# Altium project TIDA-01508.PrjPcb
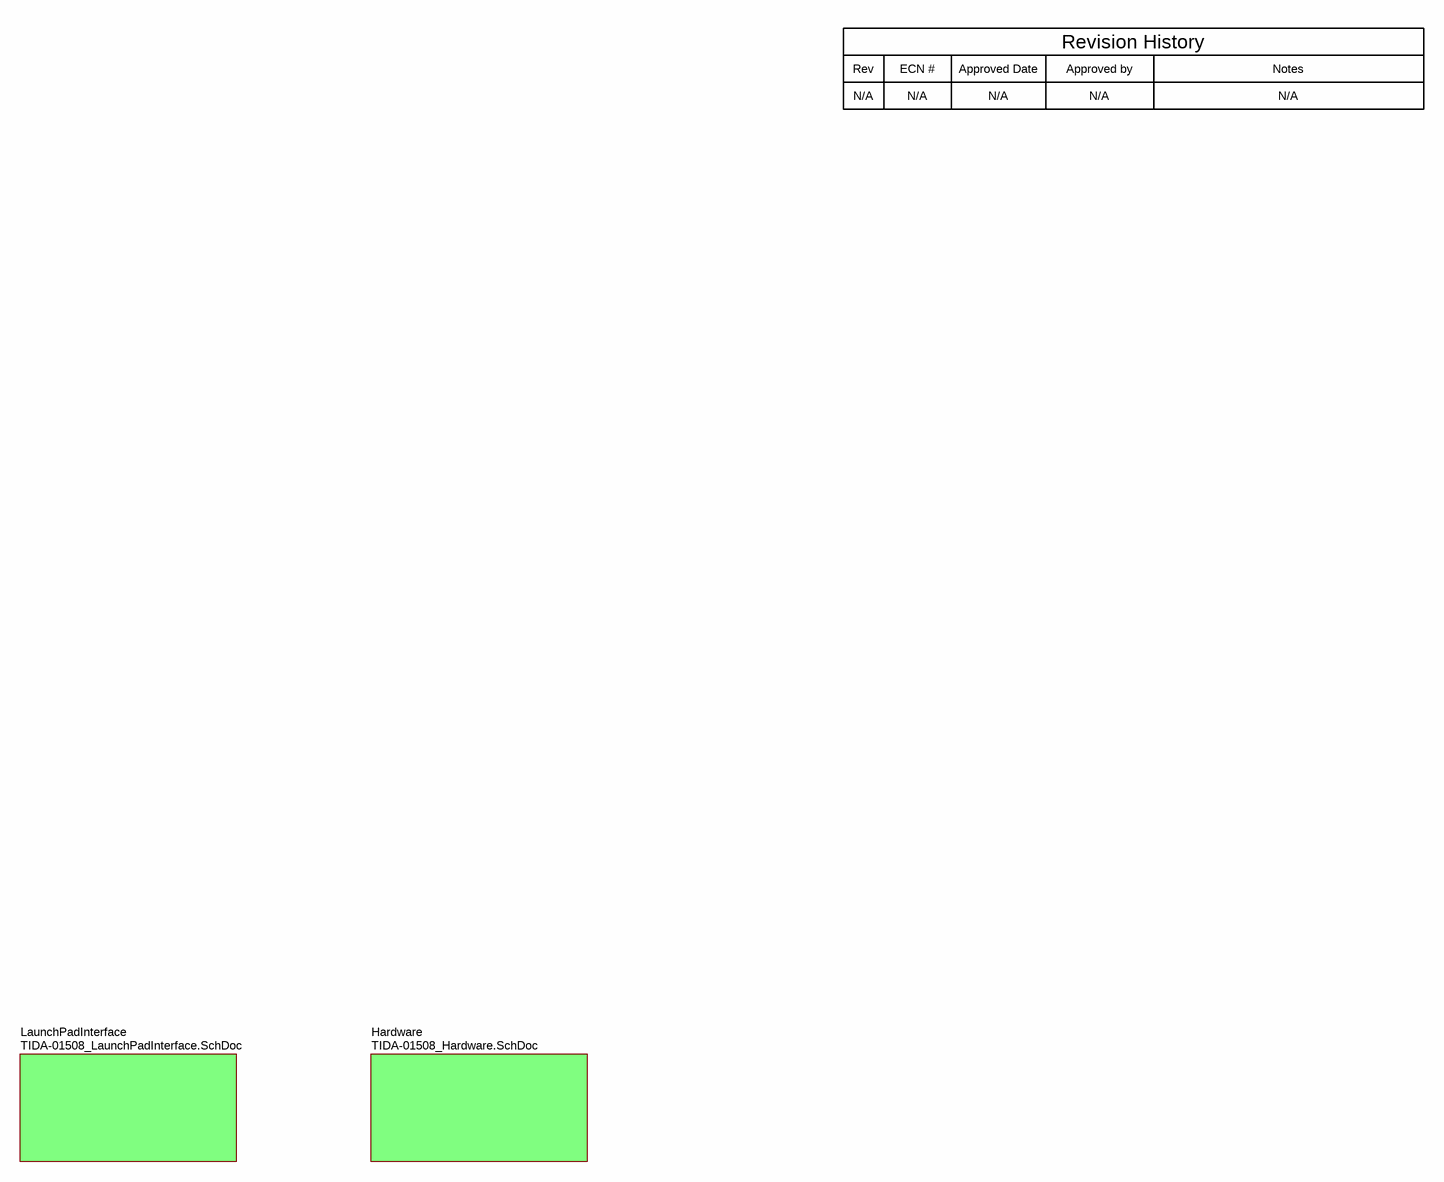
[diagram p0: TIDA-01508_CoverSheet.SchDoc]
CopyrightYear: 2017; PCB_Layout: Tobias Puetz; PCB_Rev: E1; PRJ_Customer: Public Release; PRJ_Engineer: Tobias Puetz; PRJ_Number: TIDA-01508; PRJ_Title: Sub 1W 16 Channel Isolated Digital Input Module Reference Design; SCH_Rev: E1; TechSupport: http://www.ti.com/support; TID: TIDA-01508
6 sheets, 195 parts. Net scope: strictly hierarchical (ports join the sheet entries above them; power ports are local).
Board file: TIDA-01508_PCB.PcbDoc
Sheets:
  TIDA-01508_CoverSheet.SchDoc
    Hardware = TIDA-01508_Hardware.SchDoc
    LaunchPadInterface = TIDA-01508_LaunchPadInterface.SchDoc
      InputStage = TIDA-01508_InputStage.SchDoc
        DI1 = TIDA-01508_ISO1212.SchDoc
        DI2 = TIDA-01508_ISO1212.SchDoc
        DI3 = TIDA-01508_ISO1212.SchDoc
        DI4 = TIDA-01508_ISO1212.SchDoc
        DI5 = TIDA-01508_ISO1212.SchDoc
        DI6 = TIDA-01508_ISO1212.SchDoc
        Ch7-8 = TIDA-01508_ISO1211.SchDoc
        Ch9-10 = TIDA-01508_ISO1211.SchDoc

## Sheet TIDA-01508_CoverSheet.SchDoc
size 431 x 279 mm; Date: Not shown in title block; ApprovedBy: Not shown in title block; CheckedBy: Not shown in title block; Author: Not shown in title block; CompanyName: Not shown in title block; DrawnBy: Tobias Puetz; Engineer: Not shown in title block; Organization: Not shown in title block; Address1: Not shown in title block; Address2: Not shown in title block; Address3: Not shown in title block; Address4: Not shown in title block; DocumentNumber: 1; Revision: Use project parameter SCH_Rev; SheetNumber: 1; SheetTotal: 6; PageSetup: Record=PageOptions¦CenterHorizontal=True¦CenterVertical=True¦PrintScale=1.00¦XCorrection=1.00¦YCorrection=1.00¦PrintKind=0¦BorderSize=5000000¦LeftOffset=0¦BottomOffset=0¦Orientation=2¦PaperLength=1000¦PaperWidth=1000¦Scale=100¦PaperSource=15¦PrintQuality=600¦MediaType=1¦DitherType=10¦PaperKind=Letter¦PrintScaleMode=1

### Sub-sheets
Hardware = TIDA-01508_Hardware.SchDoc: no entries
LaunchPadInterface = TIDA-01508_LaunchPadInterface.SchDoc: no entries

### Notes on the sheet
- Rev
- N/A
- ECN #
- Approved Date
- Approved by
- Revision History
- Notes

## Sheet TIDA-01508_Hardware.SchDoc
size 431 x 279 mm; Date: Not shown in title block; ApprovedBy: Not shown in title block; CheckedBy: Not shown in title block; Author: Not shown in title block; CompanyName: Not shown in title block; DrawnBy: Tobias Puetz; Engineer: Not shown in title block; Organization: Not shown in title block; Address1: Not shown in title block; Address2: Not shown in title block; Address3: Not shown in title block; Address4: Not shown in title block; DocumentNumber: 2; Revision: Use project parameter SCH_Rev; SheetNumber: 2; SheetTotal: 6; PageSetup: Record=PageOptions¦CenterHorizontal=True¦CenterVertical=True¦PrintScale=1.00¦XCorrection=1.00¦YCorrection=1.00¦PrintKind=0¦BorderSize=5000000¦LeftOffset=0¦BottomOffset=0¦Orientation=2¦PaperLength=1000¦PaperWidth=1000¦Scale=100¦PaperSource=15¦PrintQuality=600¦MediaType=1¦DitherType=10¦PaperKind=Letter¦PrintScaleMode=1
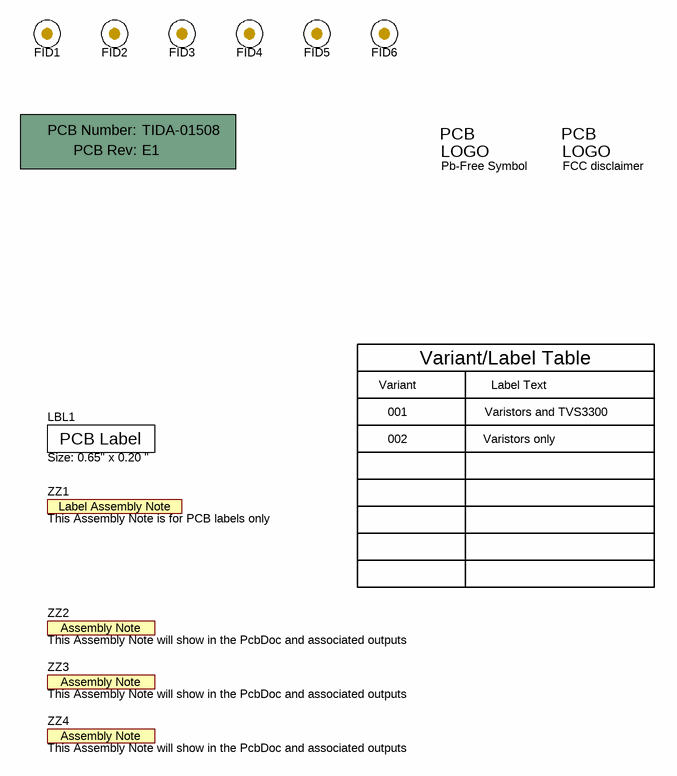
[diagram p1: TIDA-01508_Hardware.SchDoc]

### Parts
!PCB1  Printed Circuit Board  (value not drawn)  (mechanical)
FID1  Fiducial  [Fiducial10-20]  (value not drawn)
FID2  Fiducial  [Fiducial10-20]  (value not drawn)
FID3  Fiducial  [Fiducial10-20]  (value not drawn)
FID4  Fiducial  [Fiducial10-20]  (value not drawn)
FID5  Fiducial  [Fiducial10-20]  (value not drawn)
FID6  Fiducial  [Fiducial10-20]  (value not drawn)
LBL1  Size: 0.65" x 0.20 "  [Label_650x200]
Logo2  Pb-Free Symbol  [Pb-Free_Overlay_Small]  (no BOM)
Logo3  FCC disclaimer  [FCC_disclaimer]  (no BOM)
ZZ1  This Assembly Note is for PCB labels only  [AssemblyNoteLabel]  (no BOM)
ZZ2  This Assembly Note will show in the PcbDoc and associated outputs  [AssemblyNote]  (no BOM)
ZZ3  This Assembly Note will show in the PcbDoc and associated outputs  [AssemblyNote]  (no BOM)
ZZ4  This Assembly Note will show in the PcbDoc and associated outputs  [AssemblyNote]  (no BOM)

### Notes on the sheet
- Variant
- Variant/Label Table
- Label Text
- 001
- 002
- Varistors only
- Varistors and TVS3300

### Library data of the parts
!PCB1 = PCB: Manufacturer: Any; PartNumber: TIDA-01508; SymbolCreator: a0412235
FID1-FID6 = Fiducial: Fiducial mark.  There is nothing to buy or mount.; SymbolCreator: codlsc
LBL1 = THT-14-423-10: Thermal Transfer Printable Labels, 0.650" W x 0.200" H - 10,000 per roll; Manufacturer: Brady; SymbolCreator: a0412235; CompType: Label; Green_Lifecycle: Not Set; Green_REACh: Incomplete
Logo2 = Pb-Free: SymbolCreator: a0412235
Logo3 = FCC_disclaimer: SymbolCreator: a0412235
ZZ1 = AssemblyNoteLabel: SymbolCreator: a0412235
ZZ2-ZZ4 = AssemblyNote: SymbolCreator: codlsc

## Sheet TIDA-01508_LaunchPadInterface.SchDoc
size 431 x 279 mm; Date: Not shown in title block; ApprovedBy: Not shown in title block; CheckedBy: Not shown in title block; Author: Not shown in title block; CompanyName: Not shown in title block; DrawnBy: Tobias Puetz; Engineer: Not shown in title block; Organization: Not shown in title block; Address1: Not shown in title block; Address2: Not shown in title block; Address3: Not shown in title block; Address4: Not shown in title block; DocumentNumber: 3; Revision: Use project parameter SCH_Rev; SheetNumber: 3; SheetTotal: 6; PageSetup: Record=PageOptions¦CenterHorizontal=True¦CenterVertical=True¦PrintScale=1.00¦XCorrection=1.00¦YCorrection=1.00¦PrintKind=0¦BorderSize=5000000¦LeftOffset=0¦BottomOffset=0¦Orientation=2¦PaperLength=1000¦PaperWidth=1000¦Scale=100¦PaperSource=15¦PrintQuality=600¦MediaType=1¦DitherType=10¦PaperKind=Letter¦PrintScaleMode=1
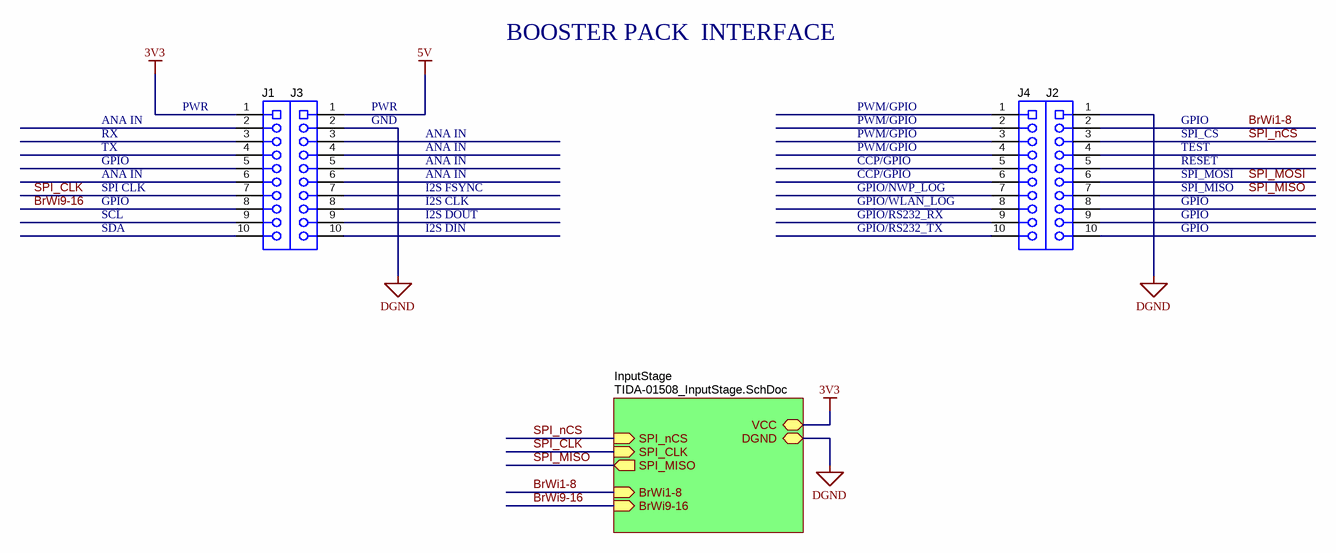
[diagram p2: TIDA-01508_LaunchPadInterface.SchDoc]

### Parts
J1  SSW-110-23-F-S  [CONN_SSW-110-23-F-S]  (value not drawn)
J2  SSW-110-23-F-S  [CONN_SSW-110-23-F-S]  (value not drawn)
J3  SSW-110-23-F-S  [CONN_SSW-110-23-F-S]  (value not drawn)
J4  SSW-110-23-F-S  [CONN_SSW-110-23-F-S]  (value not drawn)

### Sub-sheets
InputStage = TIDA-01508_InputStage.SchDoc: BrWi1-8 (in), BrWi9-16 (in), SPI_MISO (out), SPI_nCS (in), SPI_CLK (in), DGND, VCC

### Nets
3V3: J1.1 ; sheet InputStage/VCC
5V: J3.1
DGND: J2.1 J3.2 ; sheet InputStage/DGND
BrWi1-8: J2.2 ; sheet InputStage/BrWi1-8
BrWi9-16: J1.8 ; sheet InputStage/BrWi9-16
SPI_CLK: J1.7 ; sheet InputStage/SPI_CLK
SPI_MISO: J2.7 ; sheet InputStage/SPI_MISO
SPI_MOSI: J2.6
SPI_nCS: J2.3 ; sheet InputStage/SPI_nCS

Not connected (* = marked no-connect by the designer): J1 2 3 4 5 6 9 10; J2 4 5 8 9 10; J3 3 4 5 6 7 8 9 10; J4 1 2 3 4 5 6 7 8 9 10

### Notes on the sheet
- BOOSTER PACK  INTERFACE
- ANA IN
- RX
- TX
- GPIO
- PWR
- GND
- PWM/GPIO
- CCP/GPIO
- SPI_CS
- TEST
- RESET
- SPI CLK
- SCL
- SDA
- I2S FSYNC
- I2S CLK
- I2S DOUT
- I2S DIN
- GPIO/NWP_LOG
- GPIO/WLAN_LOG
- GPIO/RS232_RX
- GPIO/RS232_TX
- SPI_MOSI
- SPI_MISO

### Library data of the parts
J1-J4 = SSW-110-23-F-S: Connector, Receptacle, 100mil, 10x1, Gold plated, TH; Manufacturer: Samtec; SymbolCreator: a0411947; U/M: EA

## Sheet TIDA-01508_InputStage.SchDoc
size 431 x 279 mm; Date: Not shown in title block; ApprovedBy: Not shown in title block; CheckedBy: Not shown in title block; Author: Not shown in title block; CompanyName: Not shown in title block; DrawnBy: Tobias Puetz; Engineer: Not shown in title block; Organization: Not shown in title block; Address1: Not shown in title block; Address2: Not shown in title block; Address3: Not shown in title block; Address4: Not shown in title block; DocumentNumber: 4; Revision: Use project parameter SCH_Rev; SheetNumber: 4; SheetTotal: 6; PageSetup: Record=PageOptions¦CenterHorizontal=True¦CenterVertical=True¦PrintScale=1.00¦XCorrection=1.00¦YCorrection=1.00¦PrintKind=0¦BorderSize=5000000¦LeftOffset=0¦BottomOffset=0¦Orientation=2¦PaperLength=1000¦PaperWidth=1000¦Scale=100¦PaperSource=15¦PrintQuality=600¦MediaType=1¦DitherType=10¦PaperKind=Letter¦PrintScaleMode=1
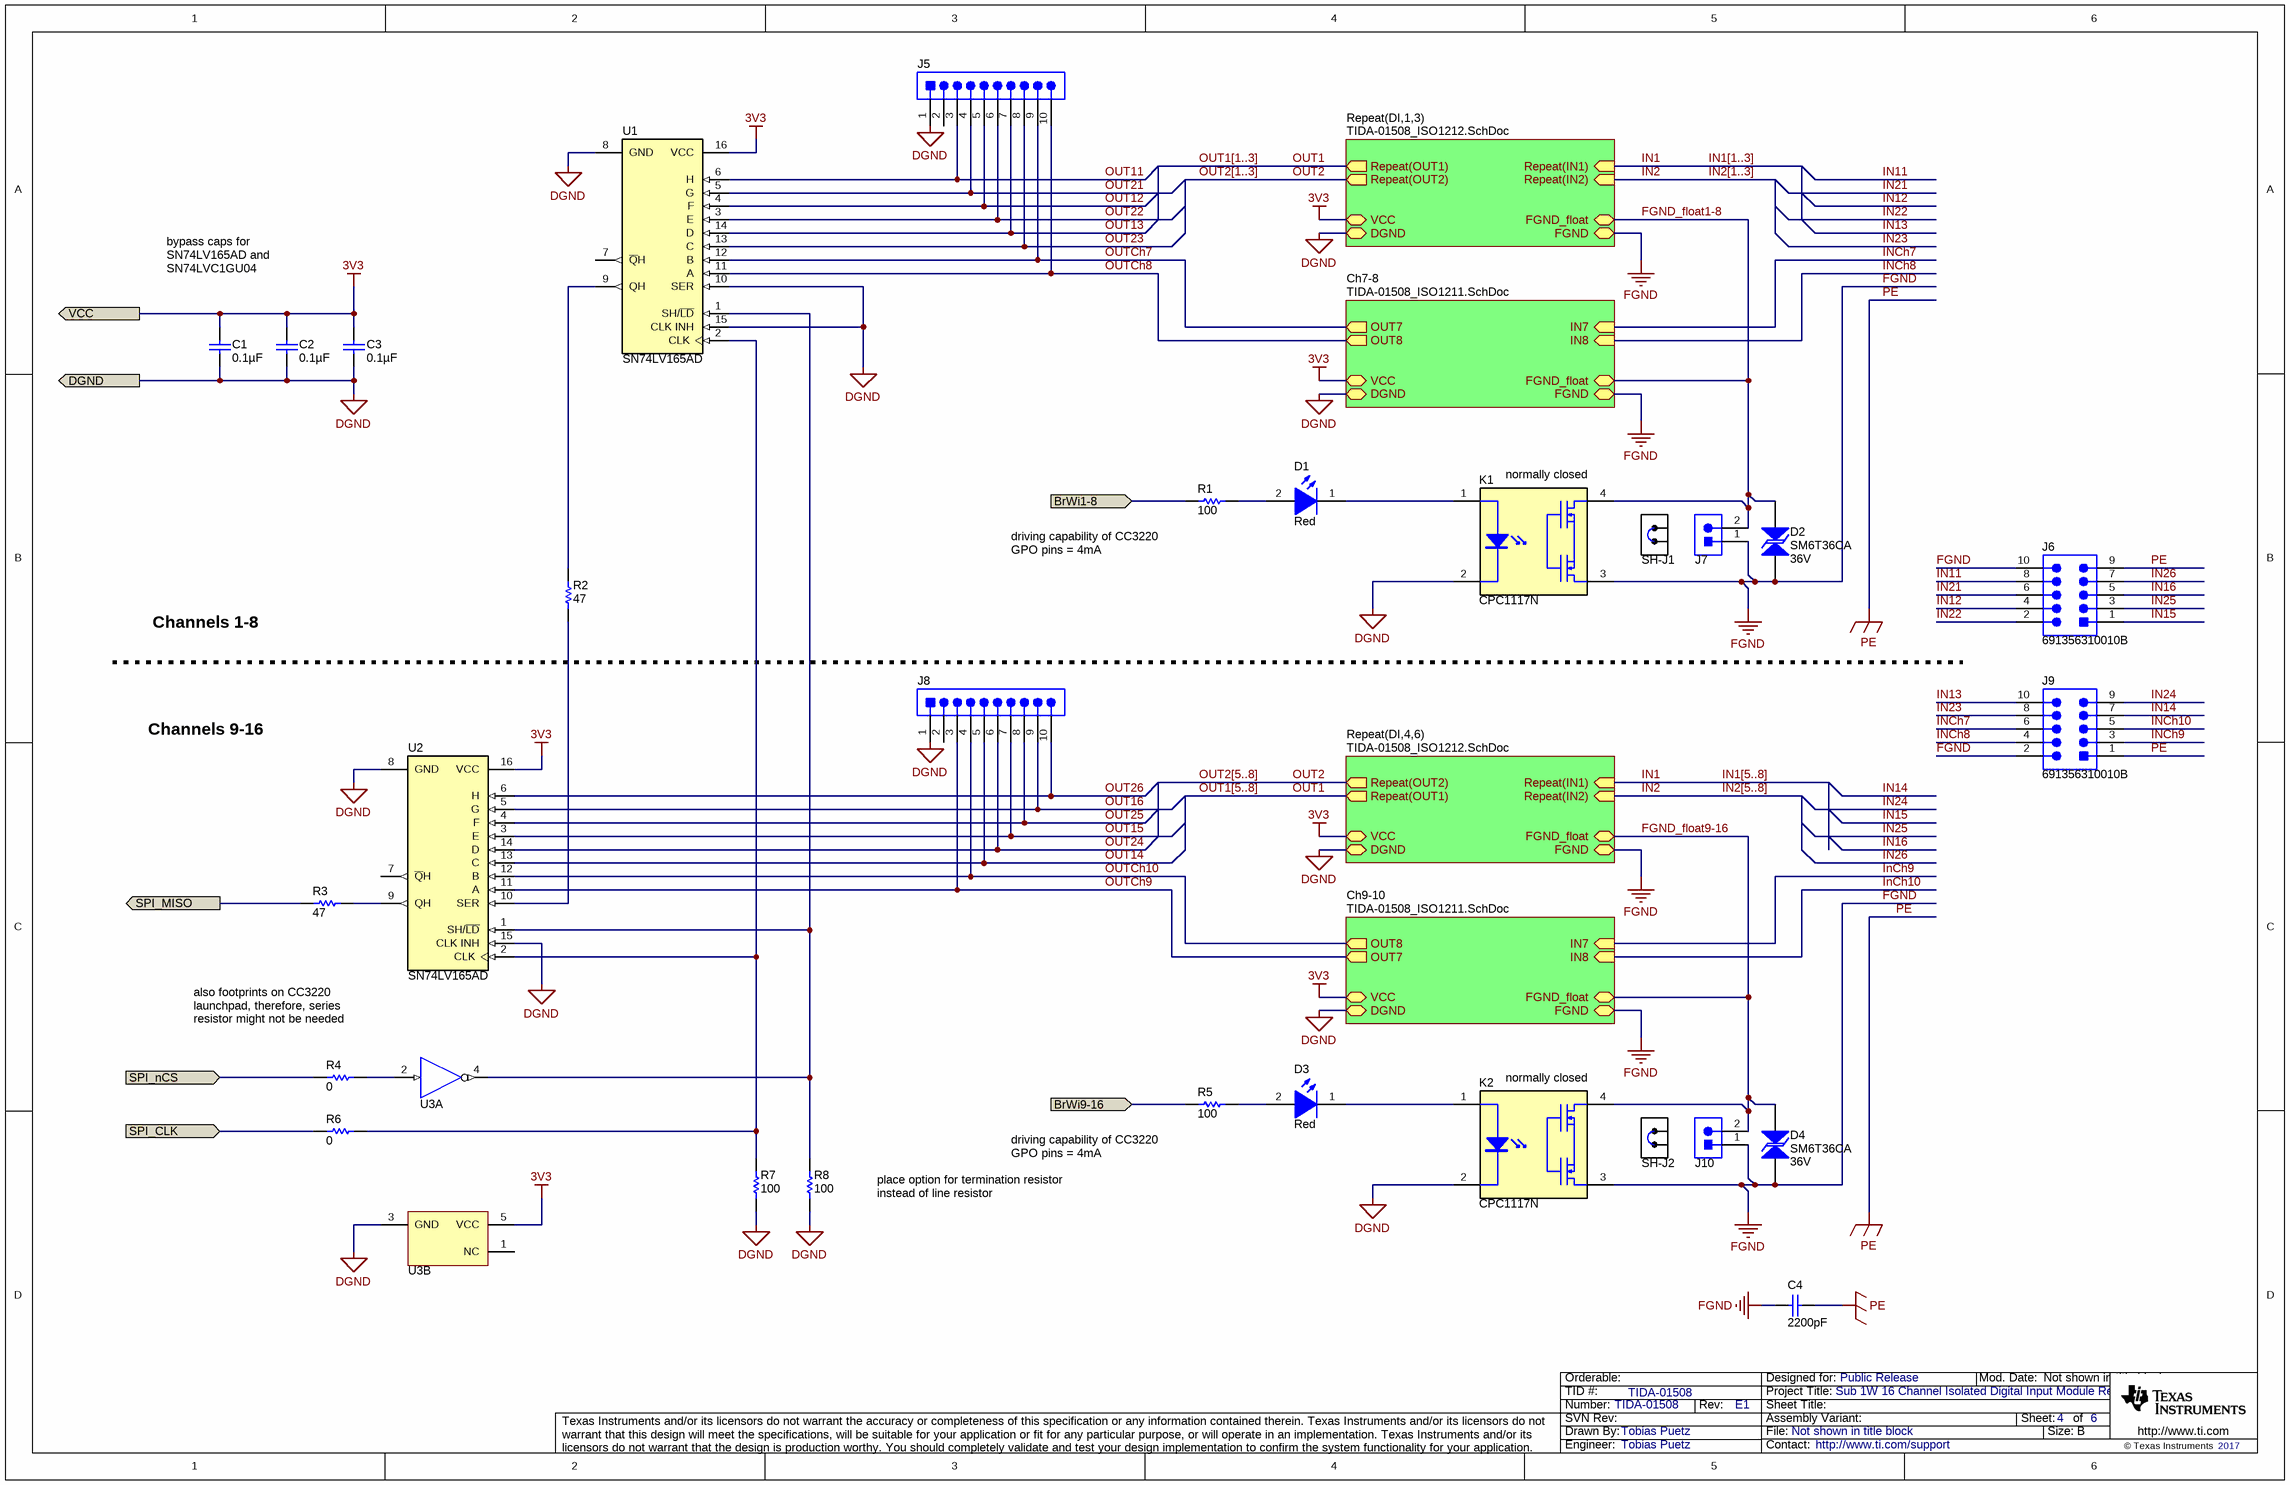
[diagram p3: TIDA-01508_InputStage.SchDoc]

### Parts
C1  ValueDisplayed: 0.1µF  [0603]  (hidden comment: GRM188R71H104KA93D)
C2  ValueDisplayed: 0.1µF  [0603]  (hidden comment: GRM188R71H104KA93D)
C3  ValueDisplayed: 0.1µF  [0603]  (hidden comment: GRM188R71H104KA93D)
C4  ValueDisplayed: 2200pF  [1210_280]  (hidden comment: 202S41W222KV4E)
D1  value Red  [WL-SMCW_RED]  (hidden comment: 150060RS75000)
D2  SM6T36CA  value 36V  [SMB-Bi]
D3  value Red  [WL-SMCW_RED]  (hidden comment: 150060RS75000)
D4  SM6T36CA  value 36V  [SMB-Bi]
J5  61301011121  [Wurth_61301011121]  (value not drawn)
J6  691356310010B  [Wurth_691356310010B]
J7  0022284023  [Molex_0022284023]  (value not drawn)
J8  61301011121  [Wurth_61301011121]  (value not drawn)
J9  691356310010B  [Wurth_691356310010B]
J10  0022284023  [Molex_0022284023]  (value not drawn)
K1  CPC1117N  [RELAY_CPC1017N]
K2  CPC1117N  [RELAY_CPC1017N]
R1  ValueDisplayed: 100  [0603]  (hidden comment: CRCW0603100RFKEA)
R2  ValueDisplayed: 47  [0603]  (hidden comment: CRCW060347R0JNEA)
R3  ValueDisplayed: 47  [0603]  (hidden comment: CRCW060347R0JNEA)
R4  ValueDisplayed: 0  [0603]  (hidden comment: CRCW06030000Z0EA)
R5  ValueDisplayed: 100  [0603]  (hidden comment: CRCW0603100RFKEA)
R6  ValueDisplayed: 0  [0603]  (hidden comment: CRCW06030000Z0EA)
R7  ValueDisplayed: 100  [0603]  (hidden comment: CRCW0603100RFKEA)
R8  ValueDisplayed: 100  [0603]  (hidden comment: CRCW0603100RFKEA)
SH-J1  60900213421  [Wurth_60900213421]  (value not drawn)
SH-J2  60900213421  [Wurth_60900213421]  (value not drawn)
U1  SN74LV165AD  [D0016A_N]
U2  SN74LV165AD  [D0016A_N]
U3  SN74LVC1GU04DBVR  [DBV0005A_N]  (value not drawn)  (parts A,B of 2)

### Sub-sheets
Ch7-8 = TIDA-01508_ISO1211.SchDoc: OUT7 (out), OUT8 (out), FGND, FGND_float, VCC, DGND, IN7 (in), IN8 (in)
Ch9-10 = TIDA-01508_ISO1211.SchDoc: OUT7 (out), OUT8 (out), FGND, FGND_float, VCC, DGND, IN7 (in), IN8 (in)
Repeat(DI,1,3) = TIDA-01508_ISO1212.SchDoc: Repeat(OUT1) (out), Repeat(OUT2) (out), Repeat(IN2) (in), Repeat(IN1) (in), FGND, FGND_float, DGND, VCC
Repeat(DI,4,6) = TIDA-01508_ISO1212.SchDoc: Repeat(OUT2) (out), Repeat(OUT1) (out), Repeat(IN2) (in), Repeat(IN1) (in), FGND_float, FGND, DGND, VCC

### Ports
BrWi1-8 (in), BrWi9-16 (in), DGND, SPI_CLK (in), SPI_MISO (out), SPI_nCS (in), VCC

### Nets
3V3: C1.1 C2.1 C3.1 U1.16(VCC) U2.16(VCC) U3.5(VCC) ; port VCC, sheet Repeat(DI,1,3)/VCC, sheet Repeat(DI,4,6)/VCC, sheet Ch7-8/VCC, sheet Ch9-10/VCC
DGND: C1.2 C2.2 C3.2 J5.1 J8.1 K1.2 K2.2 R7.1 R8.1 U1.8(GND) U1.10(SER) U1.15(CLK_INH) U2.8(GND) U2.15(CLK_INH) U3.3(GND) ; port DGND, sheet Repeat(DI,1,3)/DGND, sheet Repeat(DI,4,6)/DGND, sheet Ch7-8/DGND, sheet Ch9-10/DGND
FGND: C4.1 D2.1 D4.1 J6.10 J7.1 J9.2 J10.1 K1.3 K2.3 ; sheet Repeat(DI,1,3)/FGND, sheet Repeat(DI,4,6)/FGND, sheet Ch7-8/FGND, sheet Ch9-10/FGND
FGND_float1-8: D2.2 J7.2 K1.4 ; sheet Repeat(DI,1,3)/FGND_float, sheet Ch7-8/FGND_float
FGND_float9-16: D4.2 J10.2 K2.4 ; sheet Repeat(DI,4,6)/FGND_float, sheet Ch9-10/FGND_float
PE: C4.2 J6.9 J9.1
BrWi1-8: R1.1 ; port BrWi1-8
BrWi9-16: R5.1 ; port BrWi9-16
IN1: sheet Repeat(DI,1,3)/Repeat(IN1), sheet Repeat(DI,4,6)/Repeat(IN1)
IN2: sheet Repeat(DI,1,3)/Repeat(IN2), sheet Repeat(DI,4,6)/Repeat(IN2)
IN11: J6.8
IN12: J6.4
IN13: J9.10
IN14: J9.7
IN15: J6.1
IN16: J6.5
IN21: J6.6
IN22: J6.2
IN23: J9.8
IN24: J9.9
IN25: J6.3
IN26: J6.7
INCh7: J9.6 ; sheet Ch7-8/IN7
INCh8: J9.4 ; sheet Ch7-8/IN8
InCh9: J9.3 ; sheet Ch9-10/IN7
InCh10: J9.5 ; sheet Ch9-10/IN8
OUT1: sheet Repeat(DI,1,3)/Repeat(OUT1), sheet Repeat(DI,4,6)/Repeat(OUT1)
OUT2: sheet Repeat(DI,1,3)/Repeat(OUT2), sheet Repeat(DI,4,6)/Repeat(OUT2)
OUT11: J5.3 U1.6(H)
OUT12: J5.5 U1.4(F)
OUT13: J5.7 U1.14(D)
OUT14: J8.5 U2.13(C)
OUT15: J8.7 U2.3(E)
OUT16: J8.9 U2.5(G)
OUT21: J5.4 U1.5(G)
OUT22: J5.6 U1.3(E)
OUT23: J5.8 U1.13(C)
OUT24: J8.6 U2.14(D)
OUT25: J8.8 U2.4(F)
OUT26: J8.10 U2.6(H)
OUTCh7: J5.9 U1.12(B) ; sheet Ch7-8/OUT7
OUTCh8: J5.10 U1.11(A) ; sheet Ch7-8/OUT8
OUTCh9: J8.3 U2.11(A) ; sheet Ch9-10/OUT7
OUTCh10: J8.4 U2.12(B) ; sheet Ch9-10/OUT8
SPI_CLK: R6.1 ; port SPI_CLK
SPI_MISO: R3.1 ; port SPI_MISO
SPI_nCS: R4.1 ; port SPI_nCS
NetD1_1: D1.1(K) K1.1
NetD1_2: D1.2(A) R1.2
NetD3_1: D3.1(K) K2.1
NetD3_2: D3.2(A) R5.2
NetR2_1: R2.1 U2.10(SER)
NetR2_2: R2.2 U1.9(QH)
NetR3_2: R3.2 U2.9(QH)
NetR4_2: R4.2 U3.2(A)
NetR6_2: R6.2 R7.2 U1.2(CLK) U2.2(CLK)
NetR8_2: R8.2 U1.1(SH/~{LD}) U2.1(SH/~{LD}) U3.4(Y)

Not connected (* = marked no-connect by the designer): J5 2; J8 2; U1 7(~{Q}H); U2 7(~{Q}H); U3 1(NC)

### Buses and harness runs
bus IN1[1..3]
bus IN1[5..8]
bus IN2[1..3]
bus IN2[5..8]
bus OUT1[1..3]
bus OUT1[5..8]
bus OUT2[1..3]
bus OUT2[5..8]

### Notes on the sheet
- bypass caps for SN74LV165AD and SN74LVC1GU04
- (near K1) normally closed
- (near R1) driving capability of CC3220 GPO pins = 4mA
- Channels 1-8
- Channels 9-16
- also footprints on CC3220 launchpad, therefore, series resistor might not be needed
- (near K2) normally closed
- (near R5) driving capability of CC3220 GPO pins = 4mA
- place option for termination resistor instead of line resistor

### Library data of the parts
C1-C3 = GRM188R71H104KA93D: CAP, CERM, 0.1 µF, 50 V,+/- 10%, X7R, 0603; Manufacturer: MuRata; Polarized: N; CompType: Capacitor; Value: 0.1uF; U/M: EA; Cap_F: 0.0000001; Tolerance_%: 10; VDC_V: 50; Value2: 50V; TaMin_C: -55; TaMax_C: 125; SizeArea_mm2: 1.28; SizeAreaWB_mm2: 4.68; SizeX_mm: 1.6; SizeY_mm: 0.8; SizeZ_mm: 1; AEC Category: Q200; Green_Lifecycle: Active; Green_REACh: Passed
C4 = 202S41W222KV4E: CAP, CERM, 2200 pF, 2000 V,+/- 10%, X7R, 1210; Manufacturer: Johanson Technology; Polarized: N; CompType: Capacitor; Value: 2200pF; U/M: EA; Cap_F: 0.0000000022; Tolerance_%: 10; VDC_V: 2000; Value2: 2000V; TaMin_C: -55; TaMax_C: 125; Cap_Case: 1210; SizeArea_mm2: 8; SizeAreaWB_mm2: 14.7; SizeX_mm: 3.2; SizeY_mm: 2.5; SizeZ_mm: 2.8; AEC Category: Q200
D1 D3 = 150060RS75000: LED, Red, SMD; Manufacturer: Wurth Elektronik; Type: AlInGaP; Vf_V: 2; Value2: 2V; Io_A: 0.03; Vr_V: 5; Tjmax_C: 85; Power_TotalModule: 0.072; Value1: 0.072W; Angle: 140; U/M: EA; Green_Lifecycle: Active; Green_REACh: Passed
D2 D4 = SM6T36CA: Diode, TVS, Bi, 36 V, 64.3 Vc, SMB; Manufacturer: STMicroelectronics; U/M: EA; Vr_V: 36; Value1: W; RJA_CperW: 100; AEC Category: Q101; AEC Qualified: N
J5 J8 = 61301011121: Header, 2.54mm, 10x1, Gold, TH; Manufacturer: Wurth Elektronik; SymbolCreator: a0412235; Pitch_mm: 2.54; Gender: Male; Shrouded: N; Row_Count: 1
J6 J9 = CMP-0077239-1: Header, 3.81mm, 5x2, R/A, Tin, TH; Manufacturer: Wurth Elektronik; Pitch_mm: 3.81; Gender: Male; Cert_UL: Y; Current_A: 10A; Voltage_V: 300V; CT: False; Row_Count: 2
J7 J10 = 0022284023: Header, 2.54mm, 2x1, Tin, TH; Manufacturer: Molex; SymbolCreator: a0412235; Pitch_mm: 2.54; Gender: Male; Shrouded: N; Row_Count: 1; Current_A: 4; Voltage_V: 250; Cert_UL: Y
K1 K2 = CPC1117N: Relay, SPST-NC (1 Form B), 0.15 A, SMD; Manufacturer: IXYS; SymbolCreator: Altium; Contact Rating_A: 0.15; Time Operate (s): 0.01
R1 R5 R7 R8 = CRCW0603100RFKEA: RES, 100, 1%, 0.1 W, 0603; Manufacturer: Vishay-Dale; CompType: Resistor; Value: 100; Value_Code: 100R; Tolerance_%: 1; Power_W: 0.1; Value2: 0.1W; VDC_V: 75; TempCo: 100 ppm/C; SizeArea_mm2: 1.28; SizeX_mm: 1.6; SizeY_mm: 0.8; EIA_Code: E96; U/M: EA; AEC Category: Q200; Green_Lifecycle: Active; Green_REACh: Passed
R2 R3 = CRCW060347R0JNEA: RES, 47, 5%, 0.1 W, 0603; Manufacturer: Vishay-Dale; CompType: Resistor; Value: 47; Value_Code: 47R0; Tolerance_%: 5; Power_W: 0.1; Value2: 0.1W; VDC_V: 75; TempCo: 200 ppm/C; SizeArea_mm2: 1.28; SizeX_mm: 1.6; SizeY_mm: 0.8; SizeZ_mm: 1; EIA_Code: E24; U/M: EA; AEC Category: Q200; Green_Lifecycle: Active; Green_REACh: Passed
R4 R6 = CRCW06030000Z0EA: RES, 0, 5%, 0.1 W, 0603; Manufacturer: Vishay-Dale; CompType: Resistor; Value: 0; Value_Code: 0000; Tolerance_%: 5; Power_W: 0.1; Value2: 0.1W; VDC_V: 75; TempCo: 200 ppm/C; SizeArea_mm2: 1.28; SizeX_mm: 1.6; SizeY_mm: 0.8; SizeZ_mm: 1; EIA_Code: E24; U/M: EA; AEC Category: Q200; Green_Lifecycle: Active; Green_REACh: Passed
SH-J1 SH-J2 = 60900213421: Shunt, 2.54mm, Gold, Black; Manufacturer: Wurth Elektronik; Green_Lifecycle: Active; Green_REACh: Passed
U1 U2 = SN74LV165AD: Parallel-Load 8-Bit Shift Registers, D0016A, TUBE; Manufacturer: Texas Instruments; Alternate PartNumber: Equivalent; Technology Family: LV-A; VCC(Min)(V): 2; VCC(Max)(V): 5.5; Voltage(Nom)(V): 2.5, 3.3, 5; F @ Nom Voltage(Max)(Mhz): 70; ICC @ Nom Voltage(Max)(mA): 0.02; tpd @ Nom Voltage(Max)(ns): 28, 16.9, 13.5; Output Drive (IOL/IOH)(Max)(mA): 50/-50; Input Type: CMOS; 3-State Output: No; Rating: Catalog; Bits: 8
U3 = CMP-0051656-1: Single Inverter Gate, DBV0005A, LARGE T&R; Manufacturer: Texas Instruments; Sub-Family: Inverting Buffer/Driver; Logic: Inverting; Technology Family: LVC; Output Drive (IOL/IOH)(Max)(mA): 32/-32; Bits(#): 1; 3-State Output: No; tpd @ Nom Voltage(Max)(ns): 5.5,4.5,4.2,3.5; F @ Nom Voltage(Max)(Mhz): 150; VCC(Min)(V): 1.65; Output Type: CMOS; Voltage(Nom)(V): 1.8,2.5,3.3,5; VCC(Max)(V): 5.5; Input Type: CMOS/TTL; Rating: Catalog; ICC @ Nom Voltage(Max)(mA): 0.01

## Sheet TIDA-01508_ISO1212.SchDoc
size 431 x 279 mm; Date: Not shown in title block; ApprovedBy: Not shown in title block; CheckedBy: Not shown in title block; Author: Not shown in title block; CompanyName: Not shown in title block; DrawnBy: Tobias Puetz; Engineer: Not shown in title block; Organization: Not shown in title block; Address1: Not shown in title block; Address2: Not shown in title block; Address3: Not shown in title block; Address4: Not shown in title block; DocumentNumber: 5; Revision: Use project parameter SCH_Rev; SheetNumber: 5; SheetTotal: 6; PageSetup: Record=PageOptions¦CenterHorizontal=True¦CenterVertical=True¦PrintScale=1.00¦XCorrection=1.00¦YCorrection=1.00¦PrintKind=0¦BorderSize=5000000¦LeftOffset=0¦BottomOffset=0¦Orientation=2¦PaperLength=1000¦PaperWidth=1000¦Scale=100¦PaperSource=15¦PrintQuality=600¦MediaType=1¦DitherType=10¦PaperKind=Letter¦PrintScaleMode=1
Used 6 times, as channels LaunchPadInterface/InputStage/DI1, LaunchPadInterface/InputStage/DI2, LaunchPadInterface/InputStage/DI3, LaunchPadInterface/InputStage/DI4, LaunchPadInterface/InputStage/DI5, LaunchPadInterface/InputStage/DI6. Parts and nets are listed once, with the designators drawn on the sheet.
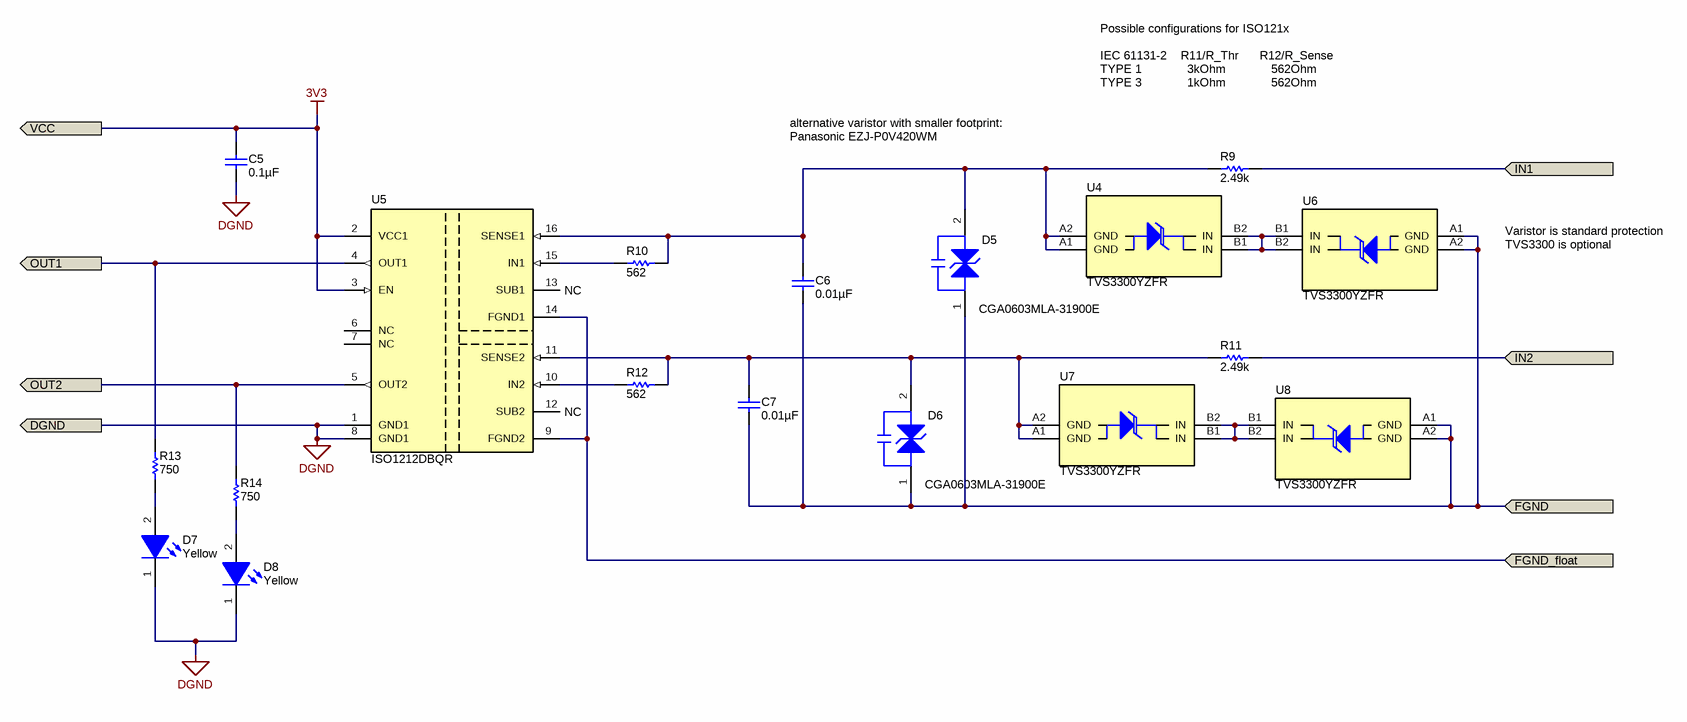
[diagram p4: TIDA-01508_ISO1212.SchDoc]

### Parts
C5  ValueDisplayed: 0.1µF  [0603]  (hidden comment: GRM188R71H104KA93D)
C6  ValueDisplayed: 0.01µF  [0402]  (hidden comment: CGA2B3X7R1H103K050BB)
C7  ValueDisplayed: 0.01µF  [0402]  (hidden comment: CGA2B3X7R1H103K050BB)
D5  CGA0603MLA-31900E  [Bourns_CGA0603MLA]
D6  CGA0603MLA-31900E  [Bourns_CGA0603MLA]
D7  value Yellow  [WL-SMCW_YELLOW]  (hidden comment: 150060YS75000)
D8  value Yellow  [WL-SMCW_YELLOW]  (hidden comment: 150060YS75000)
R9  ValueDisplayed: 2.49k  [MMB0207]  (hidden comment: MMB02070C2491FB200)
R10  ValueDisplayed: 562  [0402]  (hidden comment: CRCW0402562RFKED)
R11  ValueDisplayed: 2.49k  [MMB0207]  (hidden comment: MMB02070C2491FB200)
R12  ValueDisplayed: 562  [0402]  (hidden comment: CRCW0402562RFKED)
R13  ValueDisplayed: 750  [0603]  (hidden comment: CRCW0603750RFKEA)
R14  ValueDisplayed: 750  [0603]  (hidden comment: CRCW0603750RFKEA)
U4  TVS3300YZFR  [YZF0004-C01]
U5  ISO1212DBQR  [DBQ0016A_N]
U6  TVS3300YZFR  [YZF0004-C01]
U7  TVS3300YZFR  [YZF0004-C01]
U8  TVS3300YZFR  [YZF0004-C01]

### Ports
DGND, FGND, FGND_float, IN1 (in), IN2 (in), OUT1 (out), OUT2 (out), VCC

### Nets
3V3: C5.1 U5.2(VCC1) U5.3(EN) ; port VCC
DGND: C5.2 D7.1(K) D8.1(K) U5.1(GND1) U5.8(GND1) ; port DGND
FGND: C6.1 C7.1 D5.1(A) D6.1(A) U6.A1(GND) U6.A2(GND) U8.A1(GND) U8.A2(GND) ; port FGND
FGND_float: U5.9(FGND2) U5.14(FGND1) ; port FGND_float
IN1: R9.2 ; port IN1
IN2: R11.2 ; port IN2
OUT1: R13.2 U5.4(OUT1) ; port OUT1
OUT2: R14.2 U5.5(OUT2) ; port OUT2
NetC6_2: C6.2 D5.2(A) R9.1 R10.2 U4.A1(GND) U4.A2(GND) U5.16(SENSE1)
NetC7_2: C7.2 D6.2(A) R11.1 R12.2 U5.11(SENSE2) U7.A1(GND) U7.A2(GND)
NetD7_2: D7.2(A) R13.1
NetD8_2: D8.2(A) R14.1
NetR10_1: R10.1 U5.15(IN1)
NetR12_1: R12.1 U5.10(IN2)
NetU4_B1: U4.B1(IN) U4.B2(IN) U6.B1(IN) U6.B2(IN)
NetU7_B1: U7.B1(IN) U7.B2(IN) U8.B1(IN) U8.B2(IN)

Not connected (* = marked no-connect by the designer): U5 6(NC) 7(NC) 12(SUB2) 13(SUB1)

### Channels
LaunchPadInterface/InputStage/DI1: designators end in _DI1; ports DGND=DGND FGND=FGND FGND_float=FGND_float1-8 IN1=IN11 IN2=IN21 OUT1=OUT11 OUT2=OUT21 VCC=3V3
LaunchPadInterface/InputStage/DI2: designators end in _DI2; ports DGND=DGND FGND=FGND FGND_float=FGND_float1-8 IN1=IN12 IN2=IN22 OUT1=OUT12 OUT2=OUT22 VCC=3V3
LaunchPadInterface/InputStage/DI3: designators end in _DI3; ports DGND=DGND FGND=FGND FGND_float=FGND_float1-8 IN1=IN13 IN2=IN23 OUT1=OUT13 OUT2=OUT23 VCC=3V3
LaunchPadInterface/InputStage/DI4: designators end in _DI4; ports DGND=DGND FGND=FGND FGND_float=FGND_float9-16 IN1=IN14 IN2=IN24 OUT1=OUT14 OUT2=OUT24 VCC=3V3
LaunchPadInterface/InputStage/DI5: designators end in _DI5; ports DGND=DGND FGND=FGND FGND_float=FGND_float9-16 IN1=IN15 IN2=IN25 OUT1=OUT15 OUT2=OUT25 VCC=3V3
LaunchPadInterface/InputStage/DI6: designators end in _DI6; ports DGND=DGND FGND=FGND FGND_float=FGND_float9-16 IN1=IN16 IN2=IN26 OUT1=OUT16 OUT2=OUT26 VCC=3V3

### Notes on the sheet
- Possible configurations for ISO121x
  IEC 61131-2    R11/R_Thr      R12/R_Sense
  TYPE 1             3kOhm             562Ohm
  TYPE 3             1kOhm             562Ohm
- alternative varistor with smaller footprint: Panasonic EZJ-P0V420WM
- Varistor is standard protection
  TVS3300 is optional
- NC

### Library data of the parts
C5 = GRM188R71H104KA93D: as C1 on sheet TIDA-01508_InputStage
C6 C7 = CGA2B3X7R1H103K050BB: CAP, CERM, 0.01 µF, 50 V,+/- 10%, X7R, AEC-Q200 Grade 1, 0402; Manufacturer: TDK; Polarized: N; CompType: Capacitor; Value: 0.01uF; U/M: EA; Cap_F: 0.00000001; Tolerance_%: 10; ESR_ohm: 0.333065; Value1: 0.333065 ohm; VDC_V: 50; Value2: 50V; IRMS_A: 0.323373; TaMin_C: -55; TaMax_C: 125; SizeArea_mm2: 0.5; SizeAreaWB_mm2: 3; SizeX_mm: 1; SizeZ_mm: 0.6; AEC Category: Q200; AEC Qualified: Y; Green_Lifecycle: Active; Green_REACh: Passed
D5 D6 = CMP-0076768-1: ChipGuard Automotive MLA Series Varistor ESD Clamp Protectors; Manufacturer: Bourns; SizeAreaWB_mm2: 4.68; SizeArea_mm2: 1.28; SizeZ_mm: 0.9; SizeY_mm: 0.8; CompType: ESD Protector; SizeX_mm: 1.6
D7 D8 = 150060YS75000: LED, Yellow, SMD; Manufacturer: Wurth Elektronik; Type: AlInGaP; Vf_V: 2; Value2: 2V; Io_A: 0.02; Value1: W; U/M: EA; Green_Lifecycle: Active; Green_REACh: Passed
R9 R11 = CMP-0076703-1: RES, 2.49 k, 1%, 1 W, AEC-Q200 Grade 0, 2.2x5.8mm; Manufacturer: Vishay/Beyschlag; Value_Code: 2k49; AEC Qualified: Y; AEC Category: Q200; Value: 2.49k; EIA_Code: E96; TempCo: 50 ppm/C; AEC Grade: 0; Power_W: 1W; VDC_V: 500V; U/M: EA; CompType: Resistor
R10 R12 = CRCW0402562RFKED: RES, 562, 1%, 0.063 W, 0402; Manufacturer: Vishay-Dale; CompType: Resistor; Value: 562; Value_Code: 562R; Tolerance_%: 1; Power_W: 0.063; Value2: 0.063W; VDC_V: 50; TempCo: 100 ppm/C; SizeArea_mm2: 0.5; SizeZ_mm: 0.6; EIA_Code: E96; U/M: EA; AEC Category: Q200
R13 R14 = CRCW0603750RFKEA: RES, 750, 1%, 0.1 W, 0603; Manufacturer: Vishay-Dale; CompType: Resistor; Value: 750; Value_Code: 750R; Tolerance_%: 1; Power_W: 0.1; Value2: 0.1W; VDC_V: 75; TempCo: 100 ppm/C; SizeArea_mm2: 1.28; SizeX_mm: 1.6; SizeY_mm: 0.8; EIA_Code: E96; U/M: EA; AEC Category: Q200; Green_Lifecycle: Active; Green_REACh: Passed
U4 U6-U8 = TVS3300YZFR: 33V Precision Surge Protection Clamp, YZF0004-C01 (DSBGA-4); Alternate PartNumber: TVS3300YZFT; Manufacturer: Texas Instruments; SymbolCreator: Altium; SizeArea_mm2: 1.1984; SizeAreaWB_mm2: 4.3884; SizeX_mm: 1.12; SizeY_mm: 1.07; SizeZ_mm: 0.625; CompType: IC; U/M: EA; Green_Lifecycle: Active; Green_REACh: Passed
U5 = ISO1212DBQR: ISO1212DBQR, DBQ00016A, DBQ0016A (SSOP-16); Manufacturer: Texas Instruments; SymbolCreator: a0411947; SizeArea_mm2: 60; SizeAreaWB_mm2: 96; SizeX_mm: 6; SizeY_mm: 10; SizeZ_mm: 1.75; CompType: IC; U/M: EA

## Sheet TIDA-01508_ISO1211.SchDoc
size 431 x 279 mm; Date: Not shown in title block; ApprovedBy: Not shown in title block; CheckedBy: Not shown in title block; Author: Not shown in title block; CompanyName: Not shown in title block; DrawnBy: Tobias Puetz; Engineer: Not shown in title block; Organization: Not shown in title block; Address1: Not shown in title block; Address2: Not shown in title block; Address3: Not shown in title block; Address4: Not shown in title block; DocumentNumber: 6; Revision: Use project parameter SCH_Rev; SheetNumber: 6; SheetTotal: 6; PageSetup: Record=PageOptions¦CenterHorizontal=True¦CenterVertical=True¦PrintScale=1.00¦XCorrection=1.00¦YCorrection=1.00¦PrintKind=0¦BorderSize=5000000¦LeftOffset=0¦BottomOffset=0¦Orientation=2¦PaperLength=1000¦PaperWidth=1000¦Scale=100¦PaperSource=15¦PrintQuality=600¦MediaType=1¦DitherType=10¦PaperKind=Letter¦PrintScaleMode=1
Used 2 times, as channels LaunchPadInterface/InputStage/Ch7-8, LaunchPadInterface/InputStage/Ch9-10. Parts and nets are listed once, with the designators drawn on the sheet.
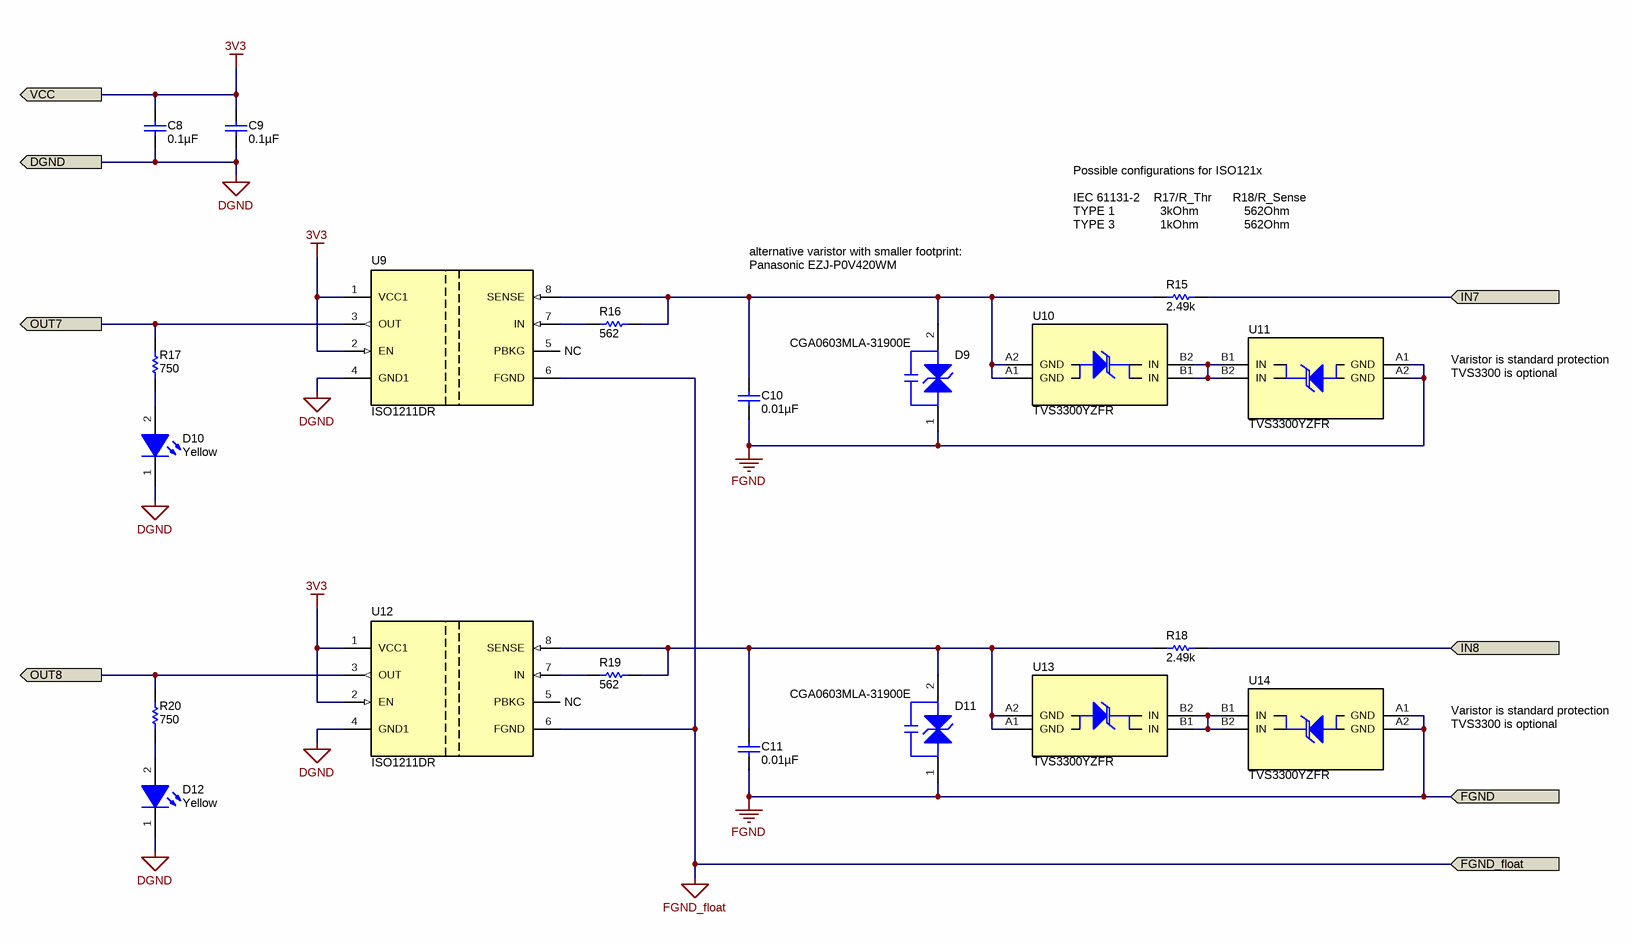
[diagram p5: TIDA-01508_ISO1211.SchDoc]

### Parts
C8  ValueDisplayed: 0.1µF  [0603]  (hidden comment: GRM188R71H104KA93D)
C9  ValueDisplayed: 0.1µF  [0603]  (hidden comment: GRM188R71H104KA93D)
C10  ValueDisplayed: 0.01µF  [0402]  (hidden comment: CGA2B3X7R1H103K050BB)
C11  ValueDisplayed: 0.01µF  [0402]  (hidden comment: CGA2B3X7R1H103K050BB)
D9  CGA0603MLA-31900E  [Bourns_CGA0603MLA]
D10  value Yellow  [WL-SMCW_YELLOW]  (hidden comment: 150060YS75000)
D11  CGA0603MLA-31900E  [Bourns_CGA0603MLA]
D12  value Yellow  [WL-SMCW_YELLOW]  (hidden comment: 150060YS75000)
R15  ValueDisplayed: 2.49k  [MMB0207]  (hidden comment: MMB02070C2491FB200)
R16  ValueDisplayed: 562  [0402]  (hidden comment: CRCW0402562RFKED)
R17  ValueDisplayed: 750  [0603]  (hidden comment: CRCW0603750RFKEA)
R18  ValueDisplayed: 2.49k  [MMB0207]  (hidden comment: MMB02070C2491FB200)
R19  ValueDisplayed: 562  [0402]  (hidden comment: CRCW0402562RFKED)
R20  ValueDisplayed: 750  [0603]  (hidden comment: CRCW0603750RFKEA)
U9  ISO1211DR  [D0008B_HV]
U10  TVS3300YZFR  [YZF0004-C01]
U11  TVS3300YZFR  [YZF0004-C01]
U12  ISO1211DR  [D0008B_HV]
U13  TVS3300YZFR  [YZF0004-C01]
U14  TVS3300YZFR  [YZF0004-C01]

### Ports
DGND, FGND, FGND_float, IN7 (in), IN8 (in), OUT7 (out), OUT8 (out), VCC

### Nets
3V3: C8.1 C9.1 U9.1(VCC1) U9.2(EN) U12.1(VCC1) U12.2(EN) ; port VCC
DGND: C8.2 C9.2 D10.1(K) D12.1(K) U9.4(GND1) U12.4(GND1) ; port DGND
FGND: C10.1 C11.1 D9.1(A) D11.1(A) U11.A1(GND) U11.A2(GND) U14.A1(GND) U14.A2(GND) ; port FGND
FGND_float: U9.6(FGND) U12.6(FGND) ; port FGND_float
IN7: R15.2 ; port IN7
IN8: R18.2 ; port IN8
OUT7: R17.2 U9.3(OUT) ; port OUT7
OUT8: R20.2 U12.3(OUT) ; port OUT8
NetC10_2: C10.2 D9.2(A) R15.1 R16.2 U9.8(SENSE) U10.A1(GND) U10.A2(GND)
NetC11_2: C11.2 D11.2(A) R18.1 R19.2 U12.8(SENSE) U13.A1(GND) U13.A2(GND)
NetD10_2: D10.2(A) R17.1
NetD12_2: D12.2(A) R20.1
NetR16_1: R16.1 U9.7(IN)
NetR19_1: R19.1 U12.7(IN)
NetU10_B1: U10.B1(IN) U10.B2(IN) U11.B1(IN) U11.B2(IN)
NetU13_B1: U13.B1(IN) U13.B2(IN) U14.B1(IN) U14.B2(IN)

Not connected (* = marked no-connect by the designer): U9 5(PBKG); U12 5(PBKG)

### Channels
LaunchPadInterface/InputStage/Ch7-8: designators end in _Ch7-8; ports DGND=DGND FGND=FGND FGND_float=FGND_float1-8 IN7=INCh7 IN8=INCh8 OUT7=OUTCh7 OUT8=OUTCh8 VCC=3V3
LaunchPadInterface/InputStage/Ch9-10: designators end in _Ch9-10; ports DGND=DGND FGND=FGND FGND_float=FGND_float9-16 IN7=InCh9 IN8=InCh10 OUT7=OUTCh9 OUT8=OUTCh10 VCC=3V3

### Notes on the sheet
- Possible configurations for ISO121x
  IEC 61131-2    R17/R_Thr      R18/R_Sense
  TYPE 1             3kOhm             562Ohm
  TYPE 3             1kOhm             562Ohm
- alternative varistor with smaller footprint: Panasonic EZJ-P0V420WM
- NC
- Varistor is standard protection
  TVS3300 is optional

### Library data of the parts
C8 C9 = GRM188R71H104KA93D: as C1 on sheet TIDA-01508_InputStage
C10 C11 = CGA2B3X7R1H103K050BB: as C6 on sheet TIDA-01508_ISO1212
D9 D11 = CMP-0076768-1: as D5 on sheet TIDA-01508_ISO1212
D10 D12 = 150060YS75000: as D7 on sheet TIDA-01508_ISO1212
R15 R18 = CMP-0076703-1: as R9 on sheet TIDA-01508_ISO1212
R16 R19 = CRCW0402562RFKED: as R10 on sheet TIDA-01508_ISO1212
R17 R20 = CRCW0603750RFKEA: as R13 on sheet TIDA-01508_ISO1212
U9 U12 = CMP-0013019-2: ISO1211DR, D0008B (SOIC-8); Manufacturer: Texas Instruments; SizeX_mm: 6; SizeY_mm: 4.9; CompType: IC; SizeZ_mm: 1.75; SizeArea_mm2: 29.4; SizeAreaWB_mm2: 55.2; U/M: EA
U10 U11 U13 U14 = TVS3300YZFR: as U4 on sheet TIDA-01508_ISO1212

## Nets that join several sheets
3V3: TIDA-01508_LaunchPadInterface (J1.1), TIDA-01508_InputStage (6 pins), LaunchPadInterface/InputStage/DI1 (C5_DI1.1 U5_DI1.2 U5_DI1.3), LaunchPadInterface/InputStage/DI2 (C5_DI2.1 U5_DI2.2 U5_DI2.3), LaunchPadInterface/InputStage/DI3 (C5_DI3.1 U5_DI3.2 U5_DI3.3), LaunchPadInterface/InputStage/DI4 (C5_DI4.1 U5_DI4.2 U5_DI4.3), LaunchPadInterface/InputStage/DI5 (C5_DI5.1 U5_DI5.2 U5_DI5.3), LaunchPadInterface/InputStage/DI6 (C5_DI6.1 U5_DI6.2 U5_DI6.3), LaunchPadInterface/InputStage/Ch7-8 (6 pins), LaunchPadInterface/InputStage/Ch9-10 (6 pins)
DGND: TIDA-01508_LaunchPadInterface (J2.1 J3.2), TIDA-01508_InputStage (15 pins), LaunchPadInterface/InputStage/DI1 (5 pins), LaunchPadInterface/InputStage/DI2 (5 pins), LaunchPadInterface/InputStage/DI3 (5 pins), LaunchPadInterface/InputStage/DI4 (5 pins), LaunchPadInterface/InputStage/DI5 (5 pins), LaunchPadInterface/InputStage/DI6 (5 pins), LaunchPadInterface/InputStage/Ch7-8 (6 pins), LaunchPadInterface/InputStage/Ch9-10 (6 pins)
FGND: TIDA-01508_InputStage (9 pins), LaunchPadInterface/InputStage/DI1 (8 pins), LaunchPadInterface/InputStage/DI2 (8 pins), LaunchPadInterface/InputStage/DI3 (8 pins), LaunchPadInterface/InputStage/DI4 (8 pins), LaunchPadInterface/InputStage/DI5 (8 pins), LaunchPadInterface/InputStage/DI6 (8 pins), LaunchPadInterface/InputStage/Ch7-8 (8 pins), LaunchPadInterface/InputStage/Ch9-10 (8 pins)
FGND_float1-8: TIDA-01508_InputStage (D2.2 J7.2 K1.4), LaunchPadInterface/InputStage/DI1 (U5_DI1.9 U5_DI1.14), LaunchPadInterface/InputStage/DI2 (U5_DI2.9 U5_DI2.14), LaunchPadInterface/InputStage/DI3 (U5_DI3.9 U5_DI3.14), LaunchPadInterface/InputStage/Ch7-8 (U9_Ch7-8.6 U12_Ch7-8.6)
FGND_float9-16: TIDA-01508_InputStage (D4.2 J10.2 K2.4), LaunchPadInterface/InputStage/DI4 (U5_DI4.9 U5_DI4.14), LaunchPadInterface/InputStage/DI5 (U5_DI5.9 U5_DI5.14), LaunchPadInterface/InputStage/DI6 (U5_DI6.9 U5_DI6.14), LaunchPadInterface/InputStage/Ch9-10 (U9_Ch9-10.6 U12_Ch9-10.6)
BrWi1-8: TIDA-01508_LaunchPadInterface (J2.2), TIDA-01508_InputStage (R1.1)
BrWi9-16: TIDA-01508_LaunchPadInterface (J1.8), TIDA-01508_InputStage (R5.1)
IN11: TIDA-01508_InputStage (J6.8), LaunchPadInterface/InputStage/DI1 (R9_DI1.2)
IN12: TIDA-01508_InputStage (J6.4), LaunchPadInterface/InputStage/DI2 (R9_DI2.2)
IN13: TIDA-01508_InputStage (J9.10), LaunchPadInterface/InputStage/DI3 (R9_DI3.2)
IN14: TIDA-01508_InputStage (J9.7), LaunchPadInterface/InputStage/DI4 (R9_DI4.2)
IN15: TIDA-01508_InputStage (J6.1), LaunchPadInterface/InputStage/DI5 (R9_DI5.2)
IN16: TIDA-01508_InputStage (J6.5), LaunchPadInterface/InputStage/DI6 (R9_DI6.2)
IN21: TIDA-01508_InputStage (J6.6), LaunchPadInterface/InputStage/DI1 (R11_DI1.2)
IN22: TIDA-01508_InputStage (J6.2), LaunchPadInterface/InputStage/DI2 (R11_DI2.2)
IN23: TIDA-01508_InputStage (J9.8), LaunchPadInterface/InputStage/DI3 (R11_DI3.2)
IN24: TIDA-01508_InputStage (J9.9), LaunchPadInterface/InputStage/DI4 (R11_DI4.2)
IN25: TIDA-01508_InputStage (J6.3), LaunchPadInterface/InputStage/DI5 (R11_DI5.2)
IN26: TIDA-01508_InputStage (J6.7), LaunchPadInterface/InputStage/DI6 (R11_DI6.2)
INCh7: TIDA-01508_InputStage (J9.6), LaunchPadInterface/InputStage/Ch7-8 (R15_Ch7-8.2)
INCh8: TIDA-01508_InputStage (J9.4), LaunchPadInterface/InputStage/Ch7-8 (R18_Ch7-8.2)
InCh9: TIDA-01508_InputStage (J9.3), LaunchPadInterface/InputStage/Ch9-10 (R15_Ch9-10.2)
InCh10: TIDA-01508_InputStage (J9.5), LaunchPadInterface/InputStage/Ch9-10 (R18_Ch9-10.2)
OUT11: TIDA-01508_InputStage (J5.3 U1.6), LaunchPadInterface/InputStage/DI1 (R13_DI1.2 U5_DI1.4)
OUT12: TIDA-01508_InputStage (J5.5 U1.4), LaunchPadInterface/InputStage/DI2 (R13_DI2.2 U5_DI2.4)
OUT13: TIDA-01508_InputStage (J5.7 U1.14), LaunchPadInterface/InputStage/DI3 (R13_DI3.2 U5_DI3.4)
OUT14: TIDA-01508_InputStage (J8.5 U2.13), LaunchPadInterface/InputStage/DI4 (R13_DI4.2 U5_DI4.4)
OUT15: TIDA-01508_InputStage (J8.7 U2.3), LaunchPadInterface/InputStage/DI5 (R13_DI5.2 U5_DI5.4)
OUT16: TIDA-01508_InputStage (J8.9 U2.5), LaunchPadInterface/InputStage/DI6 (R13_DI6.2 U5_DI6.4)
OUT21: TIDA-01508_InputStage (J5.4 U1.5), LaunchPadInterface/InputStage/DI1 (R14_DI1.2 U5_DI1.5)
OUT22: TIDA-01508_InputStage (J5.6 U1.3), LaunchPadInterface/InputStage/DI2 (R14_DI2.2 U5_DI2.5)
OUT23: TIDA-01508_InputStage (J5.8 U1.13), LaunchPadInterface/InputStage/DI3 (R14_DI3.2 U5_DI3.5)
OUT24: TIDA-01508_InputStage (J8.6 U2.14), LaunchPadInterface/InputStage/DI4 (R14_DI4.2 U5_DI4.5)
OUT25: TIDA-01508_InputStage (J8.8 U2.4), LaunchPadInterface/InputStage/DI5 (R14_DI5.2 U5_DI5.5)
OUT26: TIDA-01508_InputStage (J8.10 U2.6), LaunchPadInterface/InputStage/DI6 (R14_DI6.2 U5_DI6.5)
OUTCh7: TIDA-01508_InputStage (J5.9 U1.12), LaunchPadInterface/InputStage/Ch7-8 (R17_Ch7-8.2 U9_Ch7-8.3)
OUTCh8: TIDA-01508_InputStage (J5.10 U1.11), LaunchPadInterface/InputStage/Ch7-8 (R20_Ch7-8.2 U12_Ch7-8.3)
OUTCh9: TIDA-01508_InputStage (J8.3 U2.11), LaunchPadInterface/InputStage/Ch9-10 (R17_Ch9-10.2 U9_Ch9-10.3)
OUTCh10: TIDA-01508_InputStage (J8.4 U2.12), LaunchPadInterface/InputStage/Ch9-10 (R20_Ch9-10.2 U12_Ch9-10.3)
SPI_CLK: TIDA-01508_LaunchPadInterface (J1.7), TIDA-01508_InputStage (R6.1)
SPI_MISO: TIDA-01508_LaunchPadInterface (J2.7), TIDA-01508_InputStage (R3.1)
SPI_nCS: TIDA-01508_LaunchPadInterface (J2.3), TIDA-01508_InputStage (R4.1)

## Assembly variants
CMB-Varistor: not fitted U4_DI1 U4_DI2 U4_DI3 U4_DI4 U4_DI5 U4_DI6 U6_DI1 U6_DI2 U6_DI3 U6_DI4 U6_DI5 U6_DI6 U7_DI1 U7_DI2 U7_DI3 U7_DI4 U7_DI5 U7_DI6 U8_DI1 U8_DI2 U8_DI3 U8_DI4 U8_DI5 U8_DI6 U10_Ch7-8 U10_Ch9-10 U11_Ch7-8 U11_Ch9-10 U13_Ch7-8 U13_Ch9-10 U14_Ch7-8 U14_Ch9-10; alternate parts R9_DI1 -> CMP-0077732-1, R9_DI2 -> CMP-0077732-1, R9_DI5 -> CMP-0077732-1, R9_DI6 -> CMP-0077732-1, R9_DI4 -> CMP-0077732-1, R9_DI3 -> CMP-0077732-1, R11_DI6 -> CMP-0077732-1, R11_DI5 -> CMP-0077732-1, R11_DI2 -> CMP-0077732-1, R11_DI3 -> CMP-0077732-1, R11_DI4 -> CMP-0077732-1, R11_DI1 -> CMP-0077732-1, R15_Ch7-8 -> CMP-0077732-1, R15_Ch9-10 -> CMP-0077732-1, R18_Ch7-8 -> CMP-0077732-1, R18_Ch9-10 -> CMP-0077732-1
CMB-Varistor-TVS: not fitted D5_DI3 D5_DI4 D5_DI5 D6_DI4 D6_DI5 D6_DI6 D9_Ch9-10 D11_Ch7-8 U4_DI1 U4_DI2 U4_DI6 U6_DI1 U6_DI2 U6_DI6 U7_DI1 U7_DI2 U7_DI3 U8_DI1 U8_DI2 U8_DI3 U10_Ch7-8 U11_Ch7-8 U13_Ch9-10 U14_Ch9-10; alternate parts R9_DI2 -> CMP-0077732-1, R9_DI5 -> CMP-0077732-1, R9_DI6 -> CMP-0077732-1, R9_DI4 -> CMP-0077732-1, R9_DI3 -> CMP-0077732-1, R9_DI1 -> CMP-0077732-1, R11_DI6 -> CMP-0077732-1, R11_DI5 -> CMP-0077732-1, R11_DI2 -> CMP-0077732-1, R11_DI3 -> CMP-0077732-1, R11_DI4 -> CMP-0077732-1, R11_DI1 -> CMP-0077732-1, R15_Ch7-8 -> CMP-0077732-1, R15_Ch9-10 -> CMP-0077732-1, R18_Ch7-8 -> CMP-0077732-1, R18_Ch9-10 -> CMP-0077732-1
MMB-Varistor: not fitted U4_DI1 U4_DI2 U4_DI3 U4_DI4 U4_DI5 U4_DI6 U6_DI1 U6_DI2 U6_DI3 U6_DI4 U6_DI5 U6_DI6 U7_DI1 U7_DI2 U7_DI3 U7_DI4 U7_DI5 U7_DI6 U8_DI1 U8_DI2 U8_DI3 U8_DI4 U8_DI5 U8_DI6 U10_Ch7-8 U10_Ch9-10 U11_Ch7-8 U11_Ch9-10 U13_Ch7-8 U13_Ch9-10 U14_Ch7-8 U14_Ch9-10
MMB-Varistor-TVS: not fitted D5_DI3 D5_DI4 D5_DI5 D6_DI4 D6_DI5 D6_DI6 D9_Ch9-10 D11_Ch7-8 U4_DI1 U4_DI2 U4_DI6 U6_DI1 U6_DI2 U6_DI6 U7_DI1 U7_DI2 U7_DI3 U8_DI1 U8_DI2 U8_DI3 U10_Ch7-8 U11_Ch7-8 U13_Ch9-10 U14_Ch9-10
